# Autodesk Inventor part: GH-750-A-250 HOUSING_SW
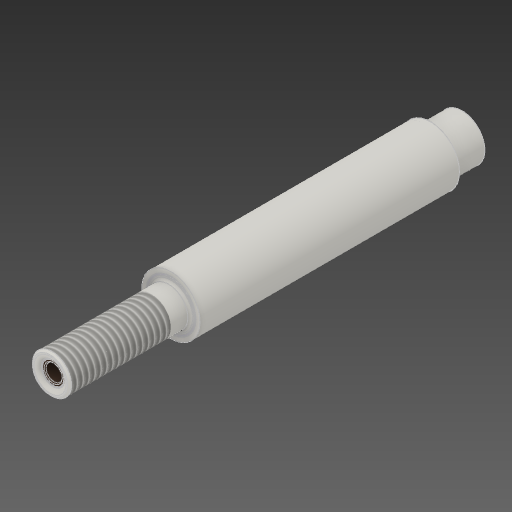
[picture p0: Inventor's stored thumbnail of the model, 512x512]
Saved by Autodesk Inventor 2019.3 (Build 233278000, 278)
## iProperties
Created: 2018-11
Part Number: GH-750-A-250 HOUSING_SW
Material: Generic
Document SubType Name: Modeling
Designer: Justin
Density: 1 g/cm^3
Appearance: Default
Author: Justin
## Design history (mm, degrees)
node "Assembly1"
body "Solid1"
node "Part1:1"
node "Part2:1"
body "Solid2"
node "Part3:1"
body "Solid3"
node "Part4:1"
body "Solid4"
node "Part5:1"
body "Solid5"
